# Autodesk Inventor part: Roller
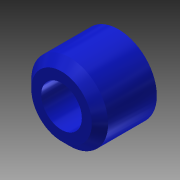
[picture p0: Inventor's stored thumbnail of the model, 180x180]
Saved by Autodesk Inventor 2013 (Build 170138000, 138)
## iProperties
Created: 2008-06
Part Number: Roller
Document SubType Name: Modeling
Designer: tangg
Density: 7.85 g/cm^3
Mass: 0.814587 g
Surface Area: 6.90277 cm^2
Volume: 0.814587 cm^3
Material: Non-Alloy Steel
Author: tangg
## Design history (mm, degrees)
sketch "Sketch1"
  geometry: C1 r 6 at (0, 0); C2 r 3.175 at (0, 0); 1 further point
  constraints: 2 centre point, 1 coincident
  dimensions: "d4" = 6.35 diameter of C2; "d5" = 12 diameter of C1
extrude "Extrusion2" new body sketch "Sketch1" distance "d2" = 8.89; taper "d3" = 0 deg
chamfer "Chamfer1" distance "d6" = 1.27; stored, may be unused: second distance "d7" = 3.175, angle "d8" = 45 deg
workpoint "Work Point1"
  workplane "Work Plane1"
body "Solid1"
other parameters: "d9" = -2.54
